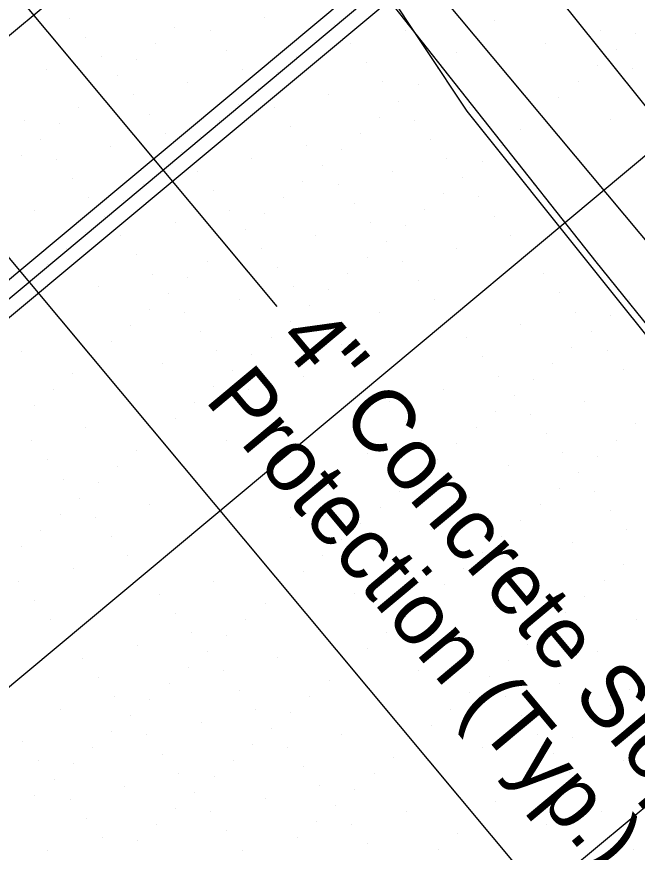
# Model space of a CAD drawing. Extents: x 2042995 to 2043795, y 305365 to 306249.
# Drawn here: x 2043404.5 to 2043429.34, y 305633.01 to 305666.44 of the extents above; entities that cross this region are included whole.
import ezdxf

# ---------------------------------------------------------------- set-up
doc = ezdxf.new("R2010")
doc.units = 0
for name, color, linetype in [('BR_AUTO DIMENSION', 7, 'Continuous'), ('BR_CENTER LINES', 7, 'Continuous'), ('BR_CONCRETE', 7, 'Continuous'), ('BR_EXIST_GROUND_CL', 7, 'Continuous'), ('BR_EXIST_GROUND_LT', 7, 'Continuous'), ('BR_EXIST_GROUND_RT', 7, 'Continuous'), ('BR_GRID DOTS', 7, 'Continuous'), ('BR_GRID LINES', 7, 'Continuous'), ('BR_STRUCTURAL STEEL', 7, 'Continuous'), ('BR_TEXT', 7, 'Continuous')]:
    doc.layers.add(name, color=color, linetype=linetype)

msp = doc.modelspace()

# ---------------------------------------------------------------- linework, layer by layer
at = {"layer": 'BR_AUTO DIMENSION'}
msp.add_line((2043414.924, 305654.848), (2043404.542, 305667.278), dxfattribs=at)
at = {"layer": 'BR_CENTER LINES'}
msp.add_line((2043453.278, 305696.145), (2043389.013, 305642.47), dxfattribs=at)
at = {"layer": 'BR_CONCRETE'}
for points in [[(2043139.109, 306017.548), (2043148.199, 306007.16), (2043160.233, 305993.368), (2043172.245, 305979.557), (2043184.234, 305965.727), (2043196.201, 305951.879), (2043208.145, 305938.012), (2043220.067, 305924.126), (2043231.966, 305910.221), (2043243.843, 305896.297), (2043255.698, 305882.355), (2043267.529, 305868.394), (2043279.339, 305854.414), (2043291.126, 305840.415), (2043302.89, 305826.398), (2043314.632, 305812.361), (2043326.352, 305798.306), (2043338.049, 305784.233), (2043349.724, 305770.14), (2043361.376, 305756.029), (2043373.005, 305741.899), (2043384.613, 305727.75), (2043396.197, 305713.582), (2043407.76, 305699.396), (2043419.299, 305685.191), (2043430.817, 305670.967), (2043442.311, 305656.724), (2043453.784, 305642.463), (2043465.234, 305628.182), (2043476.661, 305613.883), (2043488.066, 305599.566), (2043499.448, 305585.229), (2043510.808, 305570.874), (2043522.146, 305556.5), (2043533.461, 305542.107), (2043544.753, 305527.695), (2043547.219, 305524.543)], [(2043427.637, 305673.044), (2043429.921, 305670.219), (2043440.203, 305657.481)]]:
    msp.add_spline(points, degree=3, dxfattribs=at)
at = {"layer": 'BR_EXIST_GROUND_CL'}
msp.add_lwpolyline([(2043338.156, 305736.064), (2043343.356, 305729.655), (2043359.035, 305710.311), (2043370.6, 305716.249), (2043373.991, 305717.972), (2043376.489, 305716.564), (2043384.158, 305712.004), (2043388.691, 305713.145), (2043388.719, 305713.157), (2043388.724, 305713.15), (2043388.86, 305712.984), (2043404.564, 305693.828), (2043404.746, 305693.605), (2043415.952, 305679.935), (2043416.228, 305679.59), (2043431.602, 305660.44), (2043431.917, 305660.046), (2043447.252, 305640.944), (2043447.607, 305640.502), (2043462.901, 305621.449), (2043463.289, 305620.965), (2043478.169, 305602.429), (2043493.131, 305583.244)], dxfattribs=at)
at = {"layer": 'BR_EXIST_GROUND_LT'}
msp.add_lwpolyline([(2043354.799, 305715.351), (2043359.926, 305717.738), (2043364.872, 305720.524), (2043365.854, 305721.02), (2043368.102, 305722.072), (2043368.313, 305722.175), (2043369.573, 305721.387), (2043370.345, 305720.837), (2043376.349, 305716.515), (2043382.505, 305710.7), (2043387.619, 305705.755), (2043390.235, 305701.607), (2043398.668, 305691.436), (2043408.268, 305679.814), (2043412.161, 305676.205), (2043414.832, 305672.889), (2043427.68, 305656.627), (2043430.646, 305652.948), (2043443.204, 305637.057), (2043446.485, 305632.99)], dxfattribs=at)
at = {"layer": 'BR_EXIST_GROUND_RT'}
msp.add_lwpolyline([(2043346.769, 305725.658), (2043363.272, 305705.271), (2043374.342, 305711.011), (2043376.064, 305711.93), (2043378.089, 305712.973), (2043379.626, 305712.231), (2043380.137, 305712.006), (2043383.072, 305710.363), (2043386.038, 305708.267), (2043387.272, 305707.367), (2043388.278, 305706.497), (2043390.439, 305703.811), (2043392.38, 305701.256), (2043399.25, 305693.074), (2043406.074, 305684.764), (2043407.71, 305682.279), (2043408.739, 305680.988), (2043410.315, 305679.334), (2043417.513, 305670.199), (2043422.514, 305662.658), (2043427.629, 305656.269), (2043439.785, 305641.081), (2043443.164, 305636.641), (2043455.044, 305621.797)], dxfattribs=at)
at = {"layer": 'BR_GRID DOTS'}
for p, q in [((2043406.604, 305666.379), (2043406.604, 305666.379)), ((2043414.414, 305666.388), (2043414.414, 305666.388)), ((2043423.633, 305666.27), (2043423.633, 305666.27)), ((2043410.829, 305666), (2043410.829, 305666)), ((2043417.231, 305666.135), (2043417.231, 305666.135)), ((2043407.245, 305665.612), (2043407.245, 305665.612)), ((2043412.238, 305665.873), (2043412.238, 305665.873)), ((2043420.048, 305665.882), (2043420.048, 305665.882)), ((2043422.865, 305665.629), (2043422.865, 305665.629)), ((2043427.858, 305665.89), (2043427.858, 305665.89)), ((2043429.267, 305665.764), (2043429.267, 305665.764)), ((2043410.062, 305665.359), (2043410.062, 305665.359)), ((2043416.463, 305665.494), (2043416.463, 305665.494)), ((2043417.872, 305665.367), (2043417.872, 305665.367)), ((2043425.682, 305665.376), (2043425.682, 305665.376)), ((2043412.879, 305665.106), (2043412.879, 305665.106)), ((2043422.097, 305664.988), (2043422.097, 305664.988)), ((2043428.499, 305665.123), (2043428.499, 305665.123)), ((2043407.886, 305664.844), (2043407.886, 305664.844)), ((2043409.294, 305664.718), (2043409.294, 305664.718)), ((2043415.696, 305664.853), (2043415.696, 305664.853)), ((2043418.513, 305664.6), (2043418.513, 305664.6)), ((2043405.709, 305664.329), (2043405.709, 305664.329)), ((2043413.52, 305664.338), (2043413.52, 305664.338)), ((2043421.33, 305664.347), (2043421.33, 305664.347)), ((2043427.732, 305664.482), (2043427.732, 305664.482)), ((2043429.14, 305664.355), (2043429.14, 305664.355)), ((2043408.527, 305664.077), (2043408.527, 305664.077)), ((2043414.928, 305664.212), (2043414.928, 305664.212)), ((2043411.344, 305663.824), (2043411.344, 305663.824)), ((2043414.161, 305663.571), (2043414.161, 305663.571)), ((2043419.154, 305663.832), (2043419.154, 305663.832)), ((2043420.562, 305663.706), (2043420.562, 305663.706)), ((2043426.964, 305663.841), (2043426.964, 305663.841)), ((2043407.759, 305663.435), (2043407.759, 305663.435)), ((2043409.168, 305663.309), (2043409.168, 305663.309)), ((2043416.978, 305663.318), (2043416.978, 305663.318)), ((2043413.393, 305662.93), (2043413.393, 305662.93)), ((2043419.795, 305663.065), (2043419.795, 305663.065)), ((2043426.197, 305663.2), (2043426.197, 305663.2)), ((2043406.992, 305662.794), (2043406.992, 305662.794)), ((2043414.802, 305662.803), (2043414.802, 305662.803)), ((2043422.612, 305662.812), (2043422.612, 305662.812)), ((2043404.815, 305662.28), (2043404.815, 305662.28)), ((2043409.809, 305662.541), (2043409.809, 305662.541)), ((2043412.626, 305662.288), (2043412.626, 305662.288)), ((2043419.027, 305662.424), (2043419.027, 305662.424)), ((2043420.436, 305662.297), (2043420.436, 305662.297)), ((2043425.429, 305662.559), (2043425.429, 305662.559)), ((2043428.246, 305662.306), (2043428.246, 305662.306)), ((2043406.224, 305662.153), (2043406.224, 305662.153)), ((2043415.443, 305662.035), (2043415.443, 305662.035)), ((2043424.662, 305661.918), (2043424.662, 305661.918)), ((2043410.45, 305661.774), (2043410.45, 305661.774)), ((2043411.858, 305661.647), (2043411.858, 305661.647)), ((2043418.26, 305661.783), (2043418.26, 305661.783)), ((2043405.457, 305661.512), (2043405.457, 305661.512)), ((2043408.274, 305661.259), (2043408.274, 305661.259)), ((2043416.084, 305661.268), (2043416.084, 305661.268)), ((2043421.077, 305661.53), (2043421.077, 305661.53)), ((2043423.894, 305661.277), (2043423.894, 305661.277)), ((2043411.091, 305661.006), (2043411.091, 305661.006)), ((2043417.492, 305661.141), (2043417.492, 305661.141)), ((2043404.689, 305660.871), (2043404.689, 305660.871)), ((2043406.098, 305660.745), (2043406.098, 305660.745)), ((2043413.908, 305660.753), (2043413.908, 305660.753)), ((2043421.718, 305660.762), (2043421.718, 305660.762)), ((2043423.127, 305660.636), (2043423.127, 305660.636)), ((2043410.323, 305660.365), (2043410.323, 305660.365)), ((2043411.732, 305660.239), (2043411.732, 305660.239)), ((2043416.725, 305660.5), (2043416.725, 305660.5)), ((2043419.542, 305660.247), (2043419.542, 305660.247)), ((2043406.739, 305659.977), (2043406.739, 305659.977)), ((2043422.359, 305659.994), (2043422.359, 305659.994)), ((2043409.556, 305659.724), (2043409.556, 305659.724)), ((2043415.957, 305659.859), (2043415.957, 305659.859)), ((2043417.366, 305659.733), (2043417.366, 305659.733)), ((2043425.176, 305659.742), (2043425.176, 305659.742)), ((2043412.373, 305659.471), (2043412.373, 305659.471)), ((2043415.19, 305659.218), (2043415.19, 305659.218)), ((2043421.592, 305659.353), (2043421.592, 305659.353)), ((2043423, 305659.227), (2043423, 305659.227)), ((2043407.38, 305659.21), (2043407.38, 305659.21)), ((2043408.788, 305659.083), (2043408.788, 305659.083)), ((2043418.007, 305658.965), (2043418.007, 305658.965)), ((2043405.204, 305658.695), (2043405.204, 305658.695)), ((2043413.014, 305658.704), (2043413.014, 305658.704)), ((2043414.422, 305658.577), (2043414.422, 305658.577)), ((2043420.824, 305658.712), (2043420.824, 305658.712)), ((2043408.021, 305658.442), (2043408.021, 305658.442)), ((2043423.641, 305658.459), (2043423.641, 305658.459)), ((2043410.838, 305658.189), (2043410.838, 305658.189)), ((2043413.655, 305657.936), (2043413.655, 305657.936)), ((2043418.648, 305658.198), (2043418.648, 305658.198)), ((2043420.056, 305658.071), (2043420.056, 305658.071)), ((2043407.253, 305657.801), (2043407.253, 305657.801)), ((2043408.662, 305657.675), (2043408.662, 305657.675)), ((2043416.472, 305657.683), (2043416.472, 305657.683)), ((2043424.282, 305657.692), (2043424.282, 305657.692)), ((2043412.887, 305657.295), (2043412.887, 305657.295)), ((2043419.289, 305657.43), (2043419.289, 305657.43)), ((2043406.486, 305657.16), (2043406.486, 305657.16)), ((2043409.303, 305656.907), (2043409.303, 305656.907)), ((2043414.296, 305657.169), (2043414.296, 305657.169)), ((2043422.106, 305657.177), (2043422.106, 305657.177)), ((2043412.12, 305656.654), (2043412.12, 305656.654)), ((2043418.521, 305656.789), (2043418.521, 305656.789)), ((2043419.93, 305656.663), (2043419.93, 305656.663)), ((2043427.74, 305656.671), (2043427.74, 305656.671)), ((2043405.718, 305656.519), (2043405.718, 305656.519)), ((2043414.937, 305656.401), (2043414.937, 305656.401)), ((2043404.951, 305655.878), (2043404.951, 305655.878)), ((2043409.944, 305656.14), (2043409.944, 305656.14)), ((2043411.352, 305656.013), (2043411.352, 305656.013)), ((2043417.754, 305656.148), (2043417.754, 305656.148)), ((2043420.571, 305655.895), (2043420.571, 305655.895)), ((2043425.564, 305656.157), (2043425.564, 305656.157)), ((2043407.768, 305655.625), (2043407.768, 305655.625)), ((2043415.578, 305655.634), (2043415.578, 305655.634)), ((2043410.585, 305655.372), (2043410.585, 305655.372)), ((2043416.986, 305655.507), (2043416.986, 305655.507)), ((2043426.205, 305655.389), (2043426.205, 305655.389)), ((2043413.402, 305655.119), (2043413.402, 305655.119)), ((2043421.212, 305655.128), (2043421.212, 305655.128)), ((2043429.022, 305655.136), (2043429.022, 305655.136)), ((2043409.817, 305654.731), (2043409.817, 305654.731)), ((2043411.226, 305654.605), (2043411.226, 305654.605)), ((2043416.219, 305654.866), (2043416.219, 305654.866)), ((2043419.036, 305654.613), (2043419.036, 305654.613)), ((2043426.846, 305654.622), (2043426.846, 305654.622)), ((2043415.451, 305654.225), (2043415.451, 305654.225)), ((2043428.255, 305654.495), (2043428.255, 305654.495)), ((2043409.05, 305654.09), (2043409.05, 305654.09)), ((2043416.86, 305654.099), (2043416.86, 305654.099)), ((2043424.67, 305654.107), (2043424.67, 305654.107)), ((2043411.867, 305653.837), (2043411.867, 305653.837)), ((2043414.684, 305653.584), (2043414.684, 305653.584)), ((2043422.494, 305653.593), (2043422.494, 305653.593)), ((2043427.487, 305653.854), (2043427.487, 305653.854)), ((2043408.282, 305653.449), (2043408.282, 305653.449)), ((2043417.501, 305653.331), (2043417.501, 305653.331)), ((2043426.72, 305653.213), (2043426.72, 305653.213)), ((2043404.698, 305653.061), (2043404.698, 305653.061)), ((2043412.508, 305653.07), (2043412.508, 305653.07)), ((2043413.916, 305652.943), (2043413.916, 305652.943)), ((2043428.128, 305653.087), (2043428.128, 305653.087)), ((2043407.515, 305652.808), (2043407.515, 305652.808)), ((2043410.332, 305652.555), (2043410.332, 305652.555)), ((2043418.142, 305652.564), (2043418.142, 305652.564)), ((2043423.135, 305652.825), (2043423.135, 305652.825)), ((2043425.952, 305652.572), (2043425.952, 305652.572)), ((2043413.149, 305652.302), (2043413.149, 305652.302)), ((2043428.769, 305652.319), (2043428.769, 305652.319)), ((2043406.747, 305652.167), (2043406.747, 305652.167)), ((2043415.966, 305652.049), (2043415.966, 305652.049)), ((2043423.776, 305652.058), (2043423.776, 305652.058)), ((2043425.185, 305651.931), (2043425.185, 305651.931)), ((2043412.381, 305651.661), (2043412.381, 305651.661)), ((2043413.79, 305651.535), (2043413.79, 305651.535)), ((2043421.6, 305651.543), (2043421.6, 305651.543)), ((2043405.98, 305651.526), (2043405.98, 305651.526)), ((2043424.417, 305651.29), (2043424.417, 305651.29)), ((2043405.212, 305650.885), (2043405.212, 305650.885)), ((2043411.614, 305651.02), (2043411.614, 305651.02)), ((2043419.424, 305651.029), (2043419.424, 305651.029)), ((2043427.234, 305651.037), (2043427.234, 305651.037)), ((2043414.431, 305650.767), (2043414.431, 305650.767)), ((2043423.65, 305650.649), (2043423.65, 305650.649)), ((2043410.846, 305650.379), (2043410.846, 305650.379)), ((2043420.065, 305650.261), (2043420.065, 305650.261)), ((2043425.058, 305650.523), (2043425.058, 305650.523)), ((2043407.262, 305649.991), (2043407.262, 305649.991)), ((2043415.072, 305650), (2043415.072, 305650)), ((2043422.882, 305650.008), (2043422.882, 305650.008)), ((2043429.284, 305650.143), (2043429.284, 305650.143)), ((2043410.079, 305649.738), (2043410.079, 305649.738)), ((2043425.699, 305649.755), (2043425.699, 305649.755)), ((2043405.086, 305649.477), (2043405.086, 305649.477)), ((2043412.896, 305649.485), (2043412.896, 305649.485)), ((2043420.706, 305649.494), (2043420.706, 305649.494)), ((2043422.115, 305649.367), (2043422.115, 305649.367)), ((2043428.516, 305649.502), (2043428.516, 305649.502)), ((2043409.311, 305649.097), (2043409.311, 305649.097)), ((2043418.53, 305648.979), (2043418.53, 305648.979)), ((2043426.34, 305648.988), (2043426.34, 305648.988)), ((2043427.749, 305648.861), (2043427.749, 305648.861)), ((2043405.727, 305648.709), (2043405.727, 305648.709)), ((2043421.347, 305648.726), (2043421.347, 305648.726)), ((2043408.544, 305648.456), (2043408.544, 305648.456)), ((2043416.354, 305648.465), (2043416.354, 305648.465)), ((2043424.164, 305648.473), (2043424.164, 305648.473)), ((2043426.981, 305648.22), (2043426.981, 305648.22)), ((2043406.368, 305647.941), (2043406.368, 305647.941)), ((2043420.58, 305648.085), (2043420.58, 305648.085)), ((2043421.988, 305647.959), (2043421.988, 305647.959)), ((2043407.776, 305647.815), (2043407.776, 305647.815)), ((2043416.995, 305647.697), (2043416.995, 305647.697)), ((2043426.214, 305647.579), (2043426.214, 305647.579)), ((2043419.812, 305647.444), (2043419.812, 305647.444)), ((2043422.629, 305647.191), (2043422.629, 305647.191)), ((2043427.622, 305647.453), (2043427.622, 305647.453)), ((2043407.009, 305647.174), (2043407.009, 305647.174)), ((2043409.826, 305646.921), (2043409.826, 305646.921)), ((2043417.636, 305646.93), (2043417.636, 305646.93)), ((2043425.446, 305646.938), (2043425.446, 305646.938)), ((2043406.241, 305646.533), (2043406.241, 305646.533)), ((2043419.045, 305646.803), (2043419.045, 305646.803)), ((2043428.263, 305646.685), (2043428.263, 305646.685)), ((2043407.65, 305646.406), (2043407.65, 305646.406)), ((2043415.46, 305646.415), (2043415.46, 305646.415)), ((2043423.27, 305646.424), (2043423.27, 305646.424)), ((2043424.679, 305646.297), (2043424.679, 305646.297)), ((2043405.474, 305645.892), (2043405.474, 305645.892)), ((2043418.277, 305646.162), (2043418.277, 305646.162)), ((2043421.094, 305645.909), (2043421.094, 305645.909)), ((2043428.904, 305645.918), (2043428.904, 305645.918)), ((2043408.291, 305645.639), (2043408.291, 305645.639)), ((2043417.509, 305645.521), (2043417.509, 305645.521)), ((2043423.911, 305645.656), (2043423.911, 305645.656)), ((2043404.706, 305645.251), (2043404.706, 305645.251)), ((2043418.918, 305645.395), (2043418.918, 305645.395)), ((2043426.728, 305645.403), (2043426.728, 305645.403)), ((2043408.932, 305644.871), (2043408.932, 305644.871)), ((2043416.742, 305644.88), (2043416.742, 305644.88)), ((2043423.144, 305645.015), (2043423.144, 305645.015)), ((2043424.552, 305644.889), (2043424.552, 305644.889)), ((2043419.559, 305644.627), (2043419.559, 305644.627)), ((2043428.778, 305644.509), (2043428.778, 305644.509)), ((2043406.756, 305644.357), (2043406.756, 305644.357)), ((2043415.974, 305644.239), (2043415.974, 305644.239)), ((2043422.376, 305644.374), (2043422.376, 305644.374)), ((2043404.58, 305643.842), (2043404.58, 305643.842)), ((2043412.39, 305643.851), (2043412.39, 305643.851)), ((2043420.2, 305643.859), (2043420.2, 305643.859)), ((2043425.193, 305644.121), (2043425.193, 305644.121)), ((2043428.01, 305643.868), (2043428.01, 305643.868)), ((2043415.207, 305643.598), (2043415.207, 305643.598)), ((2043421.609, 305643.733), (2043421.609, 305643.733)), ((2043410.214, 305643.336), (2043410.214, 305643.336)), ((2043418.024, 305643.345), (2043418.024, 305643.345)), ((2043425.834, 305643.353), (2043425.834, 305643.353)), ((2043427.243, 305643.227), (2043427.243, 305643.227)), ((2043405.221, 305643.075), (2043405.221, 305643.075)), ((2043414.439, 305642.957), (2043414.439, 305642.957)), ((2043420.841, 305643.092), (2043420.841, 305643.092)), ((2043423.658, 305642.839), (2043423.658, 305642.839)), ((2043410.855, 305642.569), (2043410.855, 305642.569)), ((2043426.475, 305642.586), (2043426.475, 305642.586)), ((2043405.862, 305642.307), (2043405.862, 305642.307)), ((2043413.672, 305642.316), (2043413.672, 305642.316)), ((2043420.074, 305642.451), (2043420.074, 305642.451)), ((2043421.482, 305642.324), (2043421.482, 305642.324)), ((2043429.292, 305642.333), (2043429.292, 305642.333)), ((2043425.708, 305641.945), (2043425.708, 305641.945)), ((2043411.496, 305641.801), (2043411.496, 305641.801)), ((2043412.904, 305641.675), (2043412.904, 305641.675)), ((2043419.306, 305641.81), (2043419.306, 305641.81)), ((2043422.123, 305641.557), (2043422.123, 305641.557)), ((2043427.116, 305641.818), (2043427.116, 305641.818)), ((2043409.32, 305641.287), (2043409.32, 305641.287)), ((2043418.539, 305641.169), (2043418.539, 305641.169)), ((2043424.94, 305641.304), (2043424.94, 305641.304)), ((2043412.137, 305641.034), (2043412.137, 305641.034)), ((2043427.757, 305641.051), (2043427.757, 305641.051)), ((2043407.144, 305640.772), (2043407.144, 305640.772)), ((2043414.954, 305640.781), (2043414.954, 305640.781)), ((2043417.771, 305640.528), (2043417.771, 305640.528)), ((2043422.764, 305640.789), (2043422.764, 305640.789)), ((2043424.173, 305640.663), (2043424.173, 305640.663)), ((2043411.369, 305640.393), (2043411.369, 305640.393)), ((2043412.778, 305640.266), (2043412.778, 305640.266)), ((2043420.588, 305640.275), (2043420.588, 305640.275)), ((2043428.398, 305640.283), (2043428.398, 305640.283)), ((2043407.785, 305640.005), (2043407.785, 305640.005)), ((2043417.004, 305639.887), (2043417.004, 305639.887)), ((2043423.405, 305640.022), (2043423.405, 305640.022)), ((2043410.602, 305639.752), (2043410.602, 305639.752)), ((2043413.419, 305639.499), (2043413.419, 305639.499)), ((2043426.222, 305639.769), (2043426.222, 305639.769)), ((2043429.039, 305639.516), (2043429.039, 305639.516)), ((2043408.426, 305639.237), (2043408.426, 305639.237)), ((2043416.236, 305639.246), (2043416.236, 305639.246)), ((2043422.638, 305639.381), (2043422.638, 305639.381)), ((2043424.046, 305639.254), (2043424.046, 305639.254)), ((2043409.834, 305639.111), (2043409.834, 305639.111)), ((2043428.272, 305638.875), (2043428.272, 305638.875)), ((2043406.25, 305638.723), (2043406.25, 305638.723)), ((2043414.06, 305638.731), (2043414.06, 305638.731)), ((2043415.468, 305638.605), (2043415.468, 305638.605)), ((2043421.87, 305638.74), (2043421.87, 305638.74)), ((2043409.067, 305638.47), (2043409.067, 305638.47)), ((2043411.884, 305638.217), (2043411.884, 305638.217)), ((2043424.687, 305638.487), (2043424.687, 305638.487)), ((2043427.504, 305638.234), (2043427.504, 305638.234)), ((2043408.299, 305637.829), (2043408.299, 305637.829)), ((2043414.701, 305637.964), (2043414.701, 305637.964)), ((2043421.103, 305638.099), (2043421.103, 305638.099)), ((2043409.708, 305637.702), (2043409.708, 305637.702)), ((2043417.518, 305637.711), (2043417.518, 305637.711)), ((2043425.328, 305637.719), (2043425.328, 305637.719)), ((2043426.737, 305637.593), (2043426.737, 305637.593)), ((2043404.715, 305637.441), (2043404.715, 305637.441)), ((2043407.532, 305637.188), (2043407.532, 305637.188)), ((2043413.933, 305637.323), (2043413.933, 305637.323)), ((2043415.342, 305637.196), (2043415.342, 305637.196)), ((2043420.335, 305637.458), (2043420.335, 305637.458)), ((2043423.152, 305637.205), (2043423.152, 305637.205)), ((2043410.349, 305636.935), (2043410.349, 305636.935)), ((2043425.969, 305636.952), (2043425.969, 305636.952)), ((2043405.356, 305636.673), (2043405.356, 305636.673)), ((2043406.764, 305636.547), (2043406.764, 305636.547)), ((2043413.166, 305636.682), (2043413.166, 305636.682)), ((2043419.568, 305636.817), (2043419.568, 305636.817)), ((2043428.786, 305636.699), (2043428.786, 305636.699)), ((2043410.99, 305636.167), (2043410.99, 305636.167)), ((2043415.983, 305636.429), (2043415.983, 305636.429)), ((2043418.8, 305636.176), (2043418.8, 305636.176)), ((2043425.202, 305636.311), (2043425.202, 305636.311)), ((2043426.61, 305636.184), (2043426.61, 305636.184)), ((2043405.997, 305635.906), (2043405.997, 305635.906)), ((2043412.398, 305636.041), (2043412.398, 305636.041)), ((2043408.814, 305635.653), (2043408.814, 305635.653)), ((2043416.624, 305635.661), (2043416.624, 305635.661)), ((2043418.033, 305635.535), (2043418.033, 305635.535)), ((2043424.434, 305635.67), (2043424.434, 305635.67)), ((2043405.229, 305635.265), (2043405.229, 305635.265)), ((2043411.631, 305635.4), (2043411.631, 305635.4)), ((2043414.448, 305635.147), (2043414.448, 305635.147)), ((2043427.251, 305635.417), (2043427.251, 305635.417)), ((2043406.638, 305635.138), (2043406.638, 305635.138)), ((2043417.265, 305634.894), (2043417.265, 305634.894)), ((2043423.667, 305635.029), (2043423.667, 305635.029)), ((2043410.863, 305634.759), (2043410.863, 305634.759)), ((2043412.272, 305634.632), (2043412.272, 305634.632)), ((2043420.082, 305634.641), (2043420.082, 305634.641)), ((2043427.892, 305634.649), (2043427.892, 305634.649)), ((2043407.279, 305634.371), (2043407.279, 305634.371)), ((2043416.498, 305634.253), (2043416.498, 305634.253)), ((2043422.899, 305634.388), (2043422.899, 305634.388)), ((2043410.096, 305634.118), (2043410.096, 305634.118)), ((2043412.913, 305633.865), (2043412.913, 305633.865)), ((2043417.906, 305634.126), (2043417.906, 305634.126)), ((2043425.716, 305634.135), (2043425.716, 305634.135)), ((2043407.92, 305633.603), (2043407.92, 305633.603)), ((2043409.328, 305633.477), (2043409.328, 305633.477)), ((2043415.73, 305633.612), (2043415.73, 305633.612)), ((2043422.132, 305633.747), (2043422.132, 305633.747)), ((2043418.547, 305633.359), (2043418.547, 305633.359)), ((2043405.744, 305633.089), (2043405.744, 305633.089)), ((2043413.554, 305633.097), (2043413.554, 305633.097)), ((2043421.364, 305633.106), (2043421.364, 305633.106)), ((2043429.174, 305633.114), (2043429.174, 305633.114))]:
    msp.add_line(p, q, dxfattribs=at)
at = {"layer": 'BR_GRID LINES'}
for p, q in [((2043122.438, 306025.339), (2043554.061, 305508.544)), ((2043194.694, 305907.624), (2043538.711, 305495.723)), ((2043476.574, 305726.121), (2043323.07, 305597.916)), ((2043489.395, 305710.771), (2043370.429, 305611.412)), ((2043502.215, 305695.42), (2043383.25, 305596.061))]:
    msp.add_line(p, q, dxfattribs=at)
at = {"layer": 'BR_STRUCTURAL STEEL'}
for p, q in [((2043419.298, 305668.525), (2043391.655, 305645.438)), ((2043420.046, 305667.63), (2043392.403, 305644.542))]:
    msp.add_line(p, q, dxfattribs=at)

# ---------------------------------------------------------------- texts
at = {"layer": 'BR_TEXT'}
for s, p in [('4" Concrete Slope', (2043414.867, 305653.498)), ('Protection (Typ.)', (2043411.989, 305651.095))]:
    msp.add_text(s, height=2.5, rotation=309.8684, dxfattribs=at).set_placement(p)

doc.saveas('drawing.dxf')
